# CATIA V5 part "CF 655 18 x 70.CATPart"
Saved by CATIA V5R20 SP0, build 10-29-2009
Part number: CF 655 18 x 70
Definition: NONE
Nomenclature: CF 655 18 x 70
Source: Unknown
Description: CF 655 18 x 70
Bounding box of the stored display mesh (mm): x -52 to 18, y -17 to 17, z -17 to 17
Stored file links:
  C:\Users\Utente\Desktop\IO LAVORO\3D X SITO CF\X SITO\CF 655\CF 655 18 x 70.CATPart
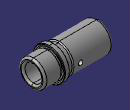
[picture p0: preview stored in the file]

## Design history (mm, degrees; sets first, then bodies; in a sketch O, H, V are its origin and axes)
Body1 "CF 655 18 x 70" (main body)
  Solid1: solid without history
